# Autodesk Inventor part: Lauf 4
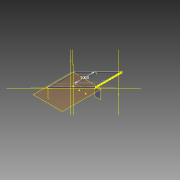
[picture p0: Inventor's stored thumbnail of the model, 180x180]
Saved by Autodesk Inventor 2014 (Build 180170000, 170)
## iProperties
Created: 2013-09
Part Number: Lauf 4
Material: Edelstahl
Document SubType Name: Modeling
Designer: Stefan Tammegger
Mass: 19379.2 g
Surface Area: 20966.2 cm^2
Volume: 2398.42 cm^3
Density: 8.08 g/cm^3
Appearance: Halbpoliert
Author: Stefan Tammegger
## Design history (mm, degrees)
node "Blöcke"
  sketch "FR 50 30 2"
    geometry: L1 (-39.377, 51.937)-(-65.377, 51.937); L2 (-67.377, 53.937)-(-67.377, 99.937); L3 (-65.377, 101.937)-(-39.377, 101.937); L4 (-37.377, 99.937)-(-37.377, 53.937); L5 (-39.377, 53.937)-(-65.377, 53.937); L6 (-65.377, 53.937)-(-65.377, 99.937); L7 (-65.377, 99.937)-(-39.377, 99.937); L8 (-39.377, 99.937)-(-39.377, 53.937); A1 r 2 centre (-39.377, 53.937) between (-39.377, 51.937) and (-37.377, 53.937); A2 r 2 centre (-39.377, 99.937) between (-37.377, 99.937) and (-39.377, 101.937); A3 r 2 centre (-65.377, 99.937) between (-65.377, 101.937) and (-67.377, 99.937); A4 r 2 centre (-65.377, 53.937) between (-67.377, 53.937) and (-65.377, 51.937); 4 further points
    constraints: 16 end point, 8 point on circle, 8 tangent, 6 point on line, 4 centre point, 4 parallel, 3 equal radius, 2 perpendicular, 1 horizontal, 1 midpoint, 3 other
    dimensions: "d0" = 30 distance of point (-67.377, 101.937) point (-37.377, 101.937); "d1" = 50 distance of point (-67.377, 51.937) point (-67.377, 101.937); "d2" = 2 distance between parallel lines of L2 L6; "d3" = 2 radius of A1
workplane "Arbeitsebene1"
sketch "Skizze1"
  geometry: L1 (0, -170)-(0, 0) reference; L2 (0, 0)-(70, 0) reference; 1 further point
  dimensions: "d4" = 30 dimension on L1; "d5" = 10 dimension on L2
extrude "Extrusion1" new body sketch "Skizze1" stored distance "d6" = 3000; taper "d7" = 0 deg
workplane "Arbeitsebene2"
sketch "Skizze2"
  geometry: L1 (117, 0)-(117, -500) reference; L2 (-1106, -60)-(-1080, -60) reference; 1 further point
  constraints: 1 horizontal
  dimensions: "d8" = 40 dimension on L1
extrude "Extrusion2" new body sketch "Skizze2" stored distance "d9" = 3000; taper "d10" = 0 deg
workplane "Arbeitsebene3"
  workaxis "Arbeitsachse1"
  workpoint "Arbeitspunkt1"
sketch "Skizze3"
  geometry: L1 (995.174, 60)-(-1119.206, 60) reference; 2 further points
  constraints: 1 horizontal
  dimensions: "d11" = 20 dimension on point (-143.546, 0)
extrude "Extrusion3" new body sketch "Skizze3" stored distance "d12" = 3000; taper "d13" = 0 deg
workplane "Arbeitsebene4"
sketch "Skizze4"
  geometry: L1 (-326.144, 183.607)-(-46.144, 183.607) reference; L2 (-326.144, 8.607)-(-326.144, 183.607) reference; L3 (798.827, 1005.387)-(-1315.553, -1122.852) reference; L4 (-326.144, 183.607)-(-326.144, 1183.607); 2 further points
  constraints: 2 end point, 1 coincident, 1 collinear
  dimensions: "d14" = 1000 distance of L1.start L4.end
  node "Referenz4"
  node "Referenz5"
workpoint "Arbeitspunkt2"
sketch "Skizze5"
  geometry: L1 (940.602, 60)-(-1173.778, 60) reference; 2 further points
  constraints: 1 horizontal
  dimensions: "d15" = 0 dimension on point (828.132, 0)
extrude "Extrusion4" new body sketch "Skizze5" distance "d16" = 3000; taper "d17" = 0 deg
workplane "Arbeitsebene5"
workplane "Arbeitsebene6"
workplane "Arbeitsebene7"
workplane "Arbeitsebene8"
feature "Trennen1"
feature "Trennen2"
feature "Trennen3"
feature "Trennen4"
feature "Trennen5"
feature "Trennen6"
feature "Trennen7"
feature "Trennen8"
sketch "Skizze6"
  geometry: L1 (0, 1344.618)-(0, 0) reference; L2 (-1301, 1002.034)-(-1223, 1002.034) reference; L3 (-1223, 1002.034)-(-1223, 1247.034) reference; L4 (-1106, 1247.034)-(-1223, 1247.034) reference; L5 (-1106, 1082.034)-(-1106, 1247.034) reference; L6 (-826, 1082.034)-(-1106, 1082.034) reference; L7 (-826, 897.034)-(-826, 1082.034) reference; L8 (-546, 897.034)-(-826, 897.034) reference; L9 (-546, 722.034)-(-546, 897.034) reference; L10 (-296, 722.034)-(-546, 722.034) reference; L11 (-296, 542.034)-(-296, 722.034) reference; L12 (-153, 542.034)-(-296, 542.034) reference; L13 (-153, 362.034)-(-153, 542.034) reference; L14 (-93, 362.034)-(-153, 362.034) reference; L15 (-93, 187.034)-(-93, 362.034) reference; L16 (-38, 187.034)-(-93, 187.034) reference; L17 (-38, 7.034)-(-38, 187.034) reference; L18 (32, 7.034)-(-38, 7.034) reference; L19 (32, -162.966)-(32, 7.034) reference; L20 (32, -332.966)-(32, -162.966) reference; L21 (32, -502.966)-(32, -332.966) reference; L22 (32, -552.966)-(32, -502.966) reference; L23 (-1155, 1199.46)-(-26, 63.061) reference; L24 (-1181, 1188.741)-(0, 0) reference; L25 (0, 157.034)-(-100, 157.034); L26 (-100, 157.034)-(-100, 7.034); L27 (-100, 7.034)-(0, 7.034); L28 (0, 7.034)-(0, 157.034); 1 further point
  constraints: 8 end point, 2 parallel, 1 collinear, 1 horizontal, 1 perpendicular
  dimensions: "d18" = 100 distance of L27.end L26.end; "d19" = 150 distance of L26.end L25.end; "d20" = 30 distance between parallel lines of L25 L16
  node "Referenz6"
workplane "Arbeitsebene9"
extrude "Extrusion5" new body sketch "Skizze6" stored distance "d21" = 3000; taper "d22" = 0 deg
hole "Bohrung1" diameter "d25" = 12; stored, may be unused: countersink angle "d29" = 90 deg, drill point angle "d31" = 118 deg; dims "d23" = 20, "d24" = 30, "d26" = 6, "d27" = 4, "d28" = 2, "d30" = 8
hole "Bohrung2" diameter "d34" = 12; stored, may be unused: countersink angle "d38" = 90 deg, drill point angle "d40" = 118 deg; dims "d32" = 20, "d33" = 20, "d35" = 6, "d36" = 4, "d37" = 2, "d39" = 8
sketch "Skizze7"
  geometry: L1 (75, 58.294)-(-42, 58.294) reference; L2 (-42, 1358.294)-(-42, 58.294) reference; L3 (-42, -186.706)-(-42, 58.294) reference; L4 (75, -106.706)-(75, 58.294) reference; L5 (355, -106.706)-(75, -106.706) reference; L6 (26, 10.72)-(1155, -1125.68) reference; L7 (0, 0)-(1181, -1188.741) reference; L8 (60, 38.294)-(-20, 38.294); L9 (-20, 38.294)-(-20, -81.706); L10 (-20, -81.706)-(60, -81.706); L11 (60, -81.706)-(60, 38.294); 1 further point
  constraints: 8 end point, 2 parallel, 1 horizontal, 1 perpendicular
  dimensions: "d41" = 80 distance of L10.end L9.end; "d42" = 120 distance of L9.end L8.end; "d43" = 15 distance between parallel lines of L4 L11; "d44" = 20 distance between parallel lines of L1 L8
  node "Referenz7"
  node "Referenz8"
  node "Referenz9"
  node "Referenz10"
  node "Referenz11"
workplane "Arbeitsebene10"
extrude "Extrusion6" new body sketch "Skizze7" stored distance "d45" = 3000; taper "d46" = 0 deg
hole "Bohrung3" diameter "d49" = 12; stored, may be unused: countersink angle "d53" = 90 deg, drill point angle "d55" = 118 deg; dims "d47" = 20, "d48" = 15, "d50" = 6, "d51" = 4, "d52" = 2, "d54" = 8
hole "Bohrung4" diameter "d58" = 12; stored, may be unused: countersink angle "d62" = 90 deg, drill point angle "d64" = 118 deg; dims "d56" = 20, "d57" = 20, "d59" = 6, "d60" = 4, "d61" = 2, "d63" = 8
sketch "Skizze8" dims "d73" = 10
  geometry: L1 (-93.546, 58)-(-93.546, 12) reference; L2 (798.132, 58)-(798.132, 12) reference; L3 (798.132, 58)-(-93.546, 58) reference; L4 (798.132, 12)-(-93.546, 12) reference; L5 (798.132, 35)-(-93.546, 35); C1 r 3 at (699.057, 35); C2 r 3 at (599.982, 35); C3 r 3 at (500.907, 35); C4 r 3 at (401.832, 35); C5 r 3 at (302.757, 35); C6 r 3 at (203.682, 35); C7 r 3 at (104.607, 35); C8 r 3 at (5.532, 35); 1 further point
  constraints: 8 centre point, 2 end point, 2 midpoint, 1 horizontal, 1 point on line, 14 other
  dimensions: "d65" = 891.67766 distance of L5.start L5.end (derived); "d66" = 6 diameter of C1; "d67" = 99.0753 distance from line of L2 C1.centre (= 0.111111 x d65); "d70" = 99.075 distance of C1.centre C2.centre
extrude "Extrusion7" new body sketch "Skizze8" stored distance "d75" = 3000; taper "d76" = 0 deg
sketch "Skizze9"
  geometry: 9 further points; 8 other entities
  constraints: 8 other
hole "Bohrung5" sketch "Skizze9" at (23, -1167.151), (23, -1026.578), (23, -886.005), (23, -745.432), (23, -604.859), (23, -464.285), (23, -323.712), (23, -183.139) diameter "d77" = 6; stored, may be unused: countersink angle "d81" = 90 deg, drill point angle "d83" = 118 deg; dims "d78" = 6, "d79" = 4, "d80" = 2, "d82" = 8
sketch "Skizze10"
  geometry: 9 further points; 8 other entities
  constraints: 8 other
hole "Bohrung6" sketch "Skizze10" at (23, -183.139), (23, -323.712), (23, -464.285), (23, -604.859), (23, -745.432), (23, -886.005), (23, -1026.578), (23, -1167.151) diameter "d84" = 6; stored, may be unused: countersink angle "d88" = 90 deg, drill point angle "d90" = 118 deg; dims "d85" = 6, "d86" = 4, "d87" = 2, "d89" = 8
workplane "Arbeitsebene11"
sketch "Skizze11"
  geometry: C1 r 3 at (699.057, 35) reference; C2 r 5 at (699.057, 35); 1 further point
  constraints: 1 centre point, 1 coincident
  dimensions: "d92" = 10 diameter of C2
extrude "Extrusion8" new body sketch "Skizze11" stored distance "d93" = 3000; taper "d94" = 0 deg
sketch "Skizze12"
  geometry: C1 r 5 at (0, 0) reference; 1 further point
hole "Bohrung7" sketch "Skizze12" at (0, 0) diameter "d95" = 6; stored, may be unused: countersink angle "d99" = 90 deg, drill point angle "d101" = 118 deg; dims "d96" = 6, "d97" = 4, "d98" = 2, "d100" = 8
workplane "Arbeitsebene12"
sketch "Skizze13"
  geometry: C1 r 3 at (699.057, 35) reference; C2 r 5 at (699.057, 35); 1 further point
  constraints: 1 centre point, 1 coincident
  dimensions: "d103" = 10 diameter of C2
extrude "Extrusion9" new body sketch "Skizze13" stored distance "d104" = 10 (= d103); taper "d105" = 0 deg
sketch "Skizze14"
  geometry: C1 r 5 at (0, 0) reference; 1 further point
hole "Bohrung8" sketch "Skizze14" at (0, 0) diameter "d106" = 6; stored, may be unused: countersink angle "d110" = 90 deg, drill point angle "d112" = 118 deg; dims "d107" = 6, "d108" = 4, "d109" = 2, "d111" = 8
pattern_linear "Rechteckige Anordnung1" dims "d115" = 140.573
node "Volumenkörper1"
node "Referenz1"
node "Referenz2"
node "Referenz3"
node "Volumenkörper2"
node "Volumenkörper3"
node "Volumenkörper4"
node "Volumenkörper5"
node "Volumenkörper6"
node "Volumenkörper7"
node "Volumenkörper8"
node "Volumenkörper9"
node "FR 50 30 2:1" dims "d4" = 30, "d5" = 10
node "FR 50 30 2:2" dims "d8" = 40
node "FR 50 30 2:3" dims "d11" = 20
node "FR 50 30 2:4" dims "d15" = 0
other parameters: "d91" = -82, "d102" = 1615
